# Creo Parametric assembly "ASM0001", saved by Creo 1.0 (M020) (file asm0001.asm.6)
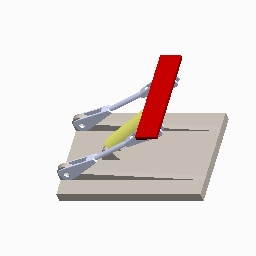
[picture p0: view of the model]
Units: millimeter Newton Second (mmNs); MM, TONNE, SECS

Other parameters: SPRING_LENGTH_UNSTRETCHED

Created from: ASSEMBLAGERELEVAGE.ASM

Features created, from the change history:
  component "SOCLE.PRT"
  component "BRAS.PRT" (7 times)
  datum axis "AA_1"
  datum axis "AA_2"
  datum plane "ADTM1"
  datum axis "AA_3"
  component "SUPPORT.PRT" (3 times)
  component "CORPS_VERIN.PRT"
  component "TIGE_PISTON.PRT" (2 times)
  feature "Ressort 1" (2 times)
  feature "Amortisseur 1" (2 times)
  component "SUPPORTBIS.PRT"
  component "SOCLEBIS"
  component "CORPS_VERIN"
  component "TIGE_PISTON"
  component "SUPPORTBIS"
  component "BRAS" (2 times)

Other named items: ASM_RIGHT, ASM_TOP, ASM_FRONT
